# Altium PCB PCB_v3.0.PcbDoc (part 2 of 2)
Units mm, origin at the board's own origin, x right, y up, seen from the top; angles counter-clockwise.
Board outline 140 x 100 mm, 2 copper layers (Top Layer, Bottom Layer); 283 components, 163 nets, 757 pads, 121 vias.
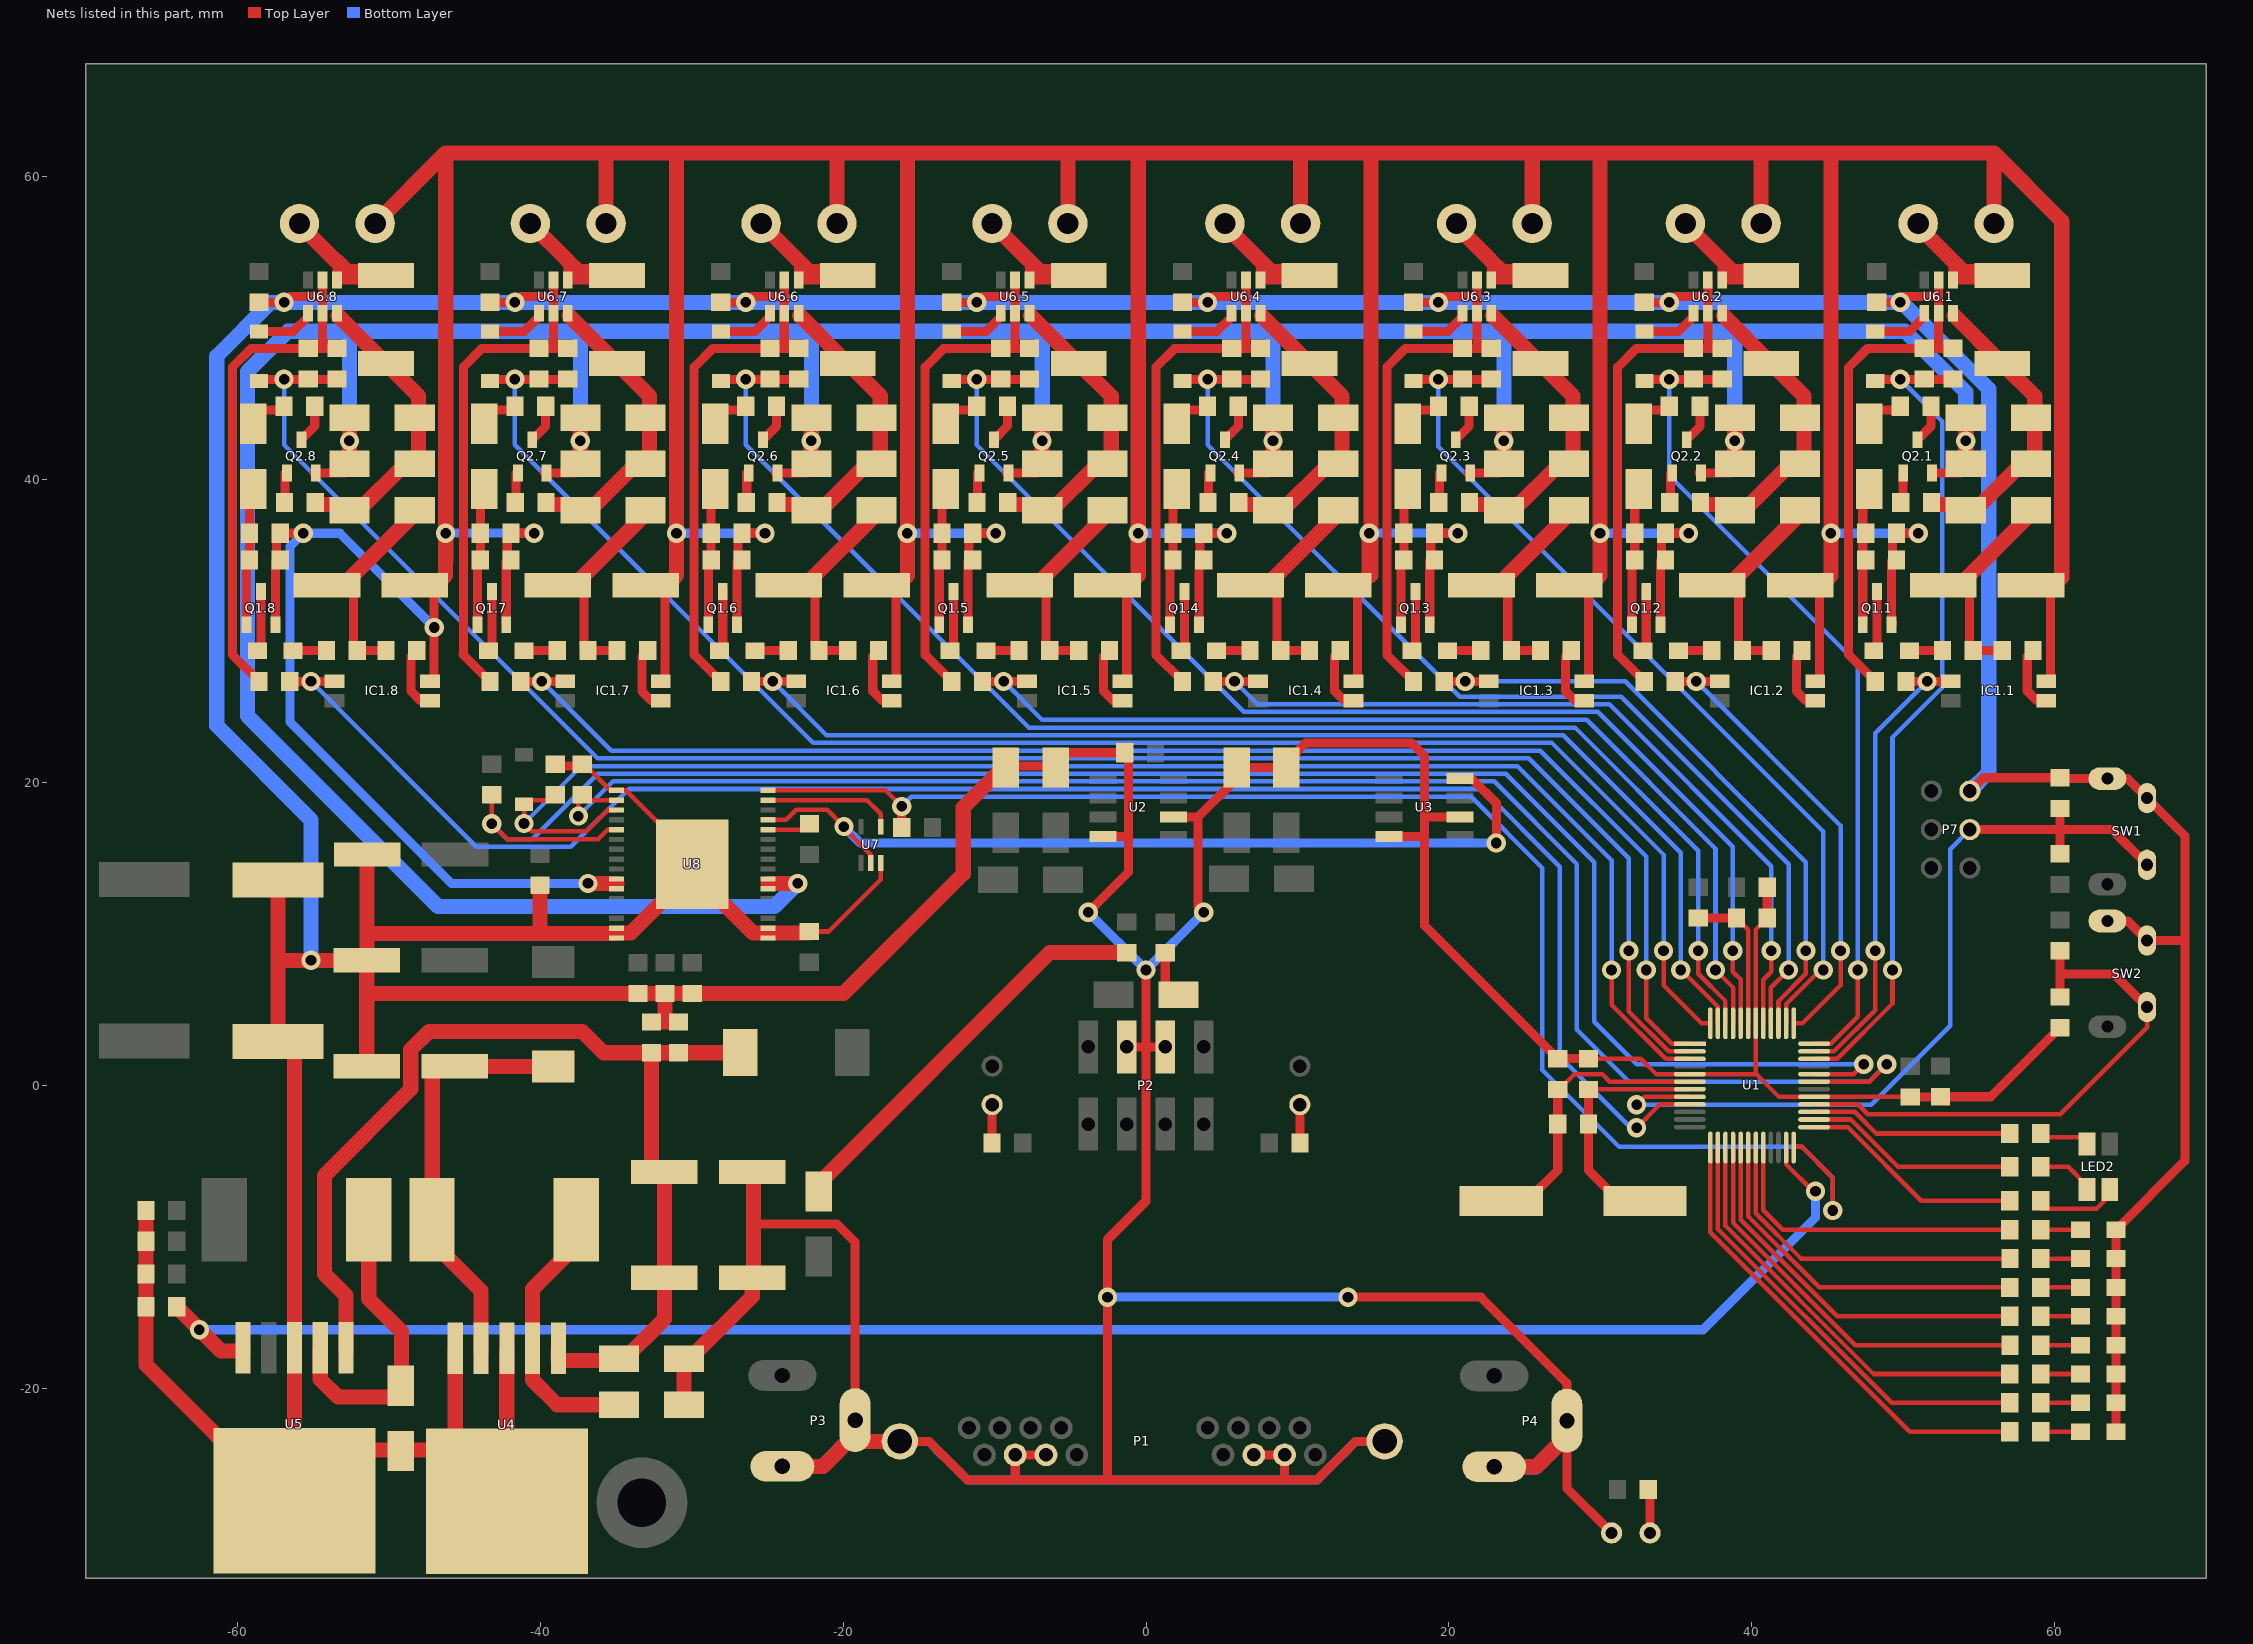
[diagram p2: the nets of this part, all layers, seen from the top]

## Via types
v1: diameter 1.27, hole 0.7, Top Layer to Bottom Layer, tented both sides, 115 vias
v2: diameter 6, hole 3.2, Top Layer to Bottom Layer, 4 vias
v3: diameter 4.05, hole 3.25, Top Layer to Bottom Layer, 2 vias

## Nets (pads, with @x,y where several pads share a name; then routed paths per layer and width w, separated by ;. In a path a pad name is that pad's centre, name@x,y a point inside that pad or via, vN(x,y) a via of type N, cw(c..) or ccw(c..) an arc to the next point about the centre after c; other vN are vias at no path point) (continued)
GND: C1.2 C2.1 C3.1 C4.2 C5.2 C6.2 C7.2 C8.2 C9.1 C10.1 C11.2 C12.2 C13.2 C14.1 C15.1 C16.1 C17.1 C18.2 C19.2 C20.2 C21.1 C22.1 C23.1 C26.1.1 C26.2.1 C26.3.1 C26.4.1 C26.5.1 C26.6.1 C26.7.1 C26.8.1 C27.1.1 C27.2.1 C27.3.1 C27.4.1 C27.5.1 C27.6.1 C27.7.1 C27.8.1 C28.1 C30.2 C31.1 D3.2 D5.1 D6.1 D7.2 D9.1 D10.1 D11.1 LED1.2 LED3.2 LED4.2 LED5.2 LED6.2 LED7.2 LED8.2 LED9.2 LED10.2 P1.0 P1.4 P1.6 P1.12 P1.14 P2.4 P2.6 P3.2 P3.3 P4.2 P4.3 P7.5 R22.1 R23.1 R29.1.1 R29.2.1 R29.3.1 R29.4.1 R29.5.1 R29.6.1 R29.7.1 R29.8.1 R32.1.1 R32.2.1 R32.3.1 R32.4.1 R32.5.1 R32.6.1 R32.7.1 R32.8.1 R33.1 SW1.1 SW1.3 SW2.1 SW2.3 U1.5 U1.29 U1.42 U2.2 U2.8 U3.2 U3.8 U4.3 U4.5 U5.3 U6.1.2 U6.1.5 U6.2.2 U6.2.5 U6.3.2 U6.3.5 U6.4.2 U6.4.5 U6.5.2 U6.5.5 U6.6.2 U6.6.5 U6.7.2 U6.7.5 U6.8.2 U6.8.5 U7.3 U8.1 U8.15 U8.16 U8.17 U8.18 U8.33 | length 1152.2
  Top Layer w0.3: R22.1@-36.956,21.081 -35.355,19.48 U8.1@-34.951,19.48 -34.335,19.48 -29.951,15.096 U8.33@-29.951,14.605 -29.951,14.118 U8.33@-29.951,14.076 ; -34.951,10.033 U8.15@-34.951,10.38 -34.626,10.055 ; -25.276,10.055 U8.18@-24.951,10.38 -24.951,10.055 ; C28.1@-22.225,10.159 -20.941,10.159 -17.511,13.589 U7.3@-17.511,14.675 U7.3@-17.511,15.056 ; C3.1@29.21,1.765 32.652,1.765 33.667,0.75 U1.5@35.9,0.75 40.271,0.75 ; C9.1@41.011,11.05 40.25,10.289 U1.42@40.25,4.1 40.25,0.771 40.271,0.75 ; C6.2@50.448,-0.765 50.433,-0.75 U1.29@44.1,-0.75 42.981,-0.75 42.981,-0.762 41.783,-0.762 40.271,0.75
  Top Layer w0.6: -60.306,28.43 -60.303,28.427 ; C26.8.1@-58.547,51.69 C26.8.1@-58.547,51.69 v1(-56.896,51.689) -56.515,52.07 -54.356,52.07 ; R29.8.1@-58.546,26.67 -60.303,28.427 ; U6.8.5@-54.356,53.17 -54.356,52.07 ; C27.8.1@-53.406,48.682 -53.447,48.641 -54.356,48.641 ; -45.067,28.43 -45.064,28.427 ; R29.7.1@-43.307,26.67 -45.064,28.427 ; C26.7.1@-43.307,51.69 C26.7.1@-43.307,51.69 v1(-41.656,51.689) -41.275,52.07 -39.116,52.07 ; U6.7.5@-39.116,53.17 -39.116,52.07 ; R33.1@-38.989,21.081 R22.1@-36.956,21.081 ; C27.7.1@-38.166,48.682 -38.207,48.641 -39.116,48.641 ; -29.827,28.43 -29.824,28.427 ; R29.6.1@-28.067,26.67 -29.824,28.427 ; C26.6.1@-28.067,51.69 C26.6.1@-28.067,51.69 v1(-26.416,51.689) -26.035,52.07 -23.876,52.07 ; -25.908,-9.144 -20.4,-9.144 -19.203,-10.341 P3.2@-19.203,-22.096 ; U6.6.5@-23.876,53.17 -23.876,52.07 ; C27.6.1@-22.926,48.682 -22.967,48.641 -23.876,48.641 ; P1.0@-16.247,-23.494 -14.331,-23.494 -11.79,-26.035 -8.632,-26.035 ; -14.586,28.43 -14.583,28.427 ; C26.5.1@-12.827,51.69 C26.5.1@-12.827,51.69 v1(-11.176,51.689) -10.795,52.07 -8.636,52.07 ; R29.5.1@-12.826,26.67 -14.583,28.427 ; D3.2@-9.327,21.082 -5.969,21.082 -5.969,21.96 -1.661,21.96 -1.396,22.225 -1.142,21.971 -1.142,16.441 ; U6.5.5@-8.636,53.17 -8.636,52.07 ; C27.5.1@-7.686,48.682 -7.727,48.641 -8.636,48.641 ; P1.6@-6.602,-24.384 P1.4@-8.632,-24.384 -8.632,-26.035 ; v1(-3.81,11.43) -1.142,14.098 -1.142,16.441 ; U2.8@-2.851,16.441 -1.142,16.441 ; P2.4@-1.27,1.397 P2.4@-1.27,2.54 0,2.54 ; v1(0,7.62) 0,2.54 ; 0.655,28.43 0.657,28.428 ; P2.6@1.27,2.54 0,2.54 ; U2.2@1.829,17.711 3.429,17.711 ; C26.4.1@2.413,51.69 C26.4.1@2.413,51.69 v1(4.064,51.689) 4.445,52.07 6.604,52.07 ; R29.4.1@2.415,26.67 0.657,28.428 ; v1(3.81,11.43) 3.429,11.811 3.429,17.711 ; U6.4.5@6.604,53.17 6.604,52.07 ; P1.12@7.118,-24.384 P1.14@9.148,-24.384 9.148,-26.035 ; C27.4.1@7.554,48.682 7.513,48.641 6.604,48.641 ; v1(13.335,-13.98) 22.108,-13.98 27.787,-19.659 P4.2@27.787,-22.127 27.787,-23.14 27.787,-26.602 LED1.2@30.73,-29.545 ; P1.0@15.753,-23.494 13.844,-23.494 12.939,-24.399 12.932,-24.399 11.453,-25.878 11.453,-25.885 11.303,-26.035 9.148,-26.035 ; 15.896,28.43 15.897,28.429 ; U3.8@16.363,16.441 18.38,16.441 ; C26.3.1@17.653,51.69 C26.3.1@17.653,51.69 v1(19.304,51.689) 19.685,52.07 21.844,52.07 ; R29.3.1@17.656,26.67 15.897,28.429 ; U3.2@20.373,17.711 18.38,17.711 ; U6.3.5@21.844,53.17 21.844,52.07 ; C27.3.1@22.794,48.682 22.753,48.641 21.844,48.641 ; C3.1@29.21,1.765 C2.1@27.178,1.765 18.38,10.563 18.38,16.441 ; C26.2.1@32.893,51.69 C26.2.1@32.893,51.69 v1(34.544,51.689) 34.925,52.07 37.084,52.07 ; R29.2.1@32.897,26.67 31.137,28.43 31.137,47.414 32.364,48.641 36.027,48.641 36.068,48.682 36.109,48.641 37.084,48.641 ; U6.2.5@37.084,53.17 37.084,52.07 ; C27.2.1@38.034,48.682 37.993,48.641 37.084,48.641 ; C9.1@41.011,11.05 C8.2@41.011,13.08 ; R29.1.1@48.138,26.67 46.377,28.431 46.377,47.393 47.625,48.641 51.267,48.641 51.308,48.682 51.349,48.641 52.324,48.641 ; C26.1.1@48.244,51.688 48.246,51.69 v1(49.784,51.69) 49.784,51.815 50.039,52.07 52.324,52.07 ; C6.2@50.448,-0.765 52.436,-0.765 C7.2@52.451,-0.75 55.764,-0.75 C5.2@60.325,3.811 ; U6.1.5@52.324,53.17 52.324,52.07 ; C27.1.1@53.274,48.682 53.233,48.641 52.324,48.641 ; P7.5@54.385,19.431 55.262,20.308 C4.2@60.325,20.308 60.383,20.25 SW1.3@63.457,20.25 64.796,20.25 SW1.1@66.083,18.964 68.58,16.467 68.58,9.566 ; SW2.3@63.457,10.852 64.796,10.852 SW2.1@66.083,9.566 68.58,9.566 ; LED10.2@64.04,-22.86 LED9.2@64.04,-20.955 LED8.2@64.04,-19.05 LED7.2@64.04,-17.145 LED6.2@64.04,-15.24 LED5.2@64.04,-13.335 LED4.2@64.04,-11.43 LED3.2@64.04,-9.525 68.58,-4.985 68.58,9.566 ; -60.303,28.427 -60.303,47.414 -59.076,48.641 -55.413,48.641 -55.372,48.682 -55.331,48.641 -54.356,48.641 ; -54.356,48.641 U6.8.2@-54.356,50.97 -54.356,52.07 ; -45.064,28.427 -45.064,46.122 -45.063,46.123 -45.063,47.414 -43.836,48.641 -40.173,48.641 -40.132,48.682 -40.091,48.641 -39.116,48.641 ; -39.116,48.641 U6.7.2@-39.116,50.97 -39.116,52.07 ; -29.824,28.427 -29.824,46.122 -29.823,46.123 -29.823,47.414 -28.596,48.641 -24.933,48.641 -24.892,48.682 -24.851,48.641 -23.876,48.641 ; -23.876,48.641 U6.6.2@-23.876,50.97 -23.876,52.07 ; -14.583,28.427 -14.583,47.414 -13.356,48.641 -9.693,48.641 -9.652,48.682 -9.611,48.641 -8.636,48.641 ; -8.636,48.641 U6.5.2@-8.636,50.97 -8.636,52.07 ; -8.632,-26.035 -2.54,-26.035 ; -2.54,-26.035 9.148,-26.035 ; -2.54,-26.035 v1(-2.54,-13.98) -2.54,-10.17 0,-7.63 0,2.54 ; 0.657,28.428 0.657,47.414 1.884,48.641 5.547,48.641 5.588,48.682 5.629,48.641 6.604,48.641 ; 3.429,17.711 5.978,20.26 D9.1@5.978,20.98 D7.2@9.271,20.98 9.77,20.98 9.77,21.837 10.539,22.606 17.526,22.606 18.38,21.752 18.38,17.711 ; 6.604,48.641 U6.4.2@6.604,50.97 6.604,52.07 ; 15.897,28.429 15.897,47.414 17.124,48.641 20.787,48.641 20.828,48.682 20.869,48.641 21.844,48.641 ; 18.38,16.441 18.38,17.711 ; 21.844,48.641 U6.3.2@21.844,50.97 21.844,52.07 ; 37.084,48.641 U6.2.2@37.084,50.97 37.084,52.07 ; 52.324,48.641 U6.1.2@52.324,50.97 52.324,52.07
  Top Layer w1: C23.1@-66.015,-12.573 R23.1@-66.015,-14.605 -66.015,-18.44 -56.829,-27.626 -56.818,-27.543 U5.3@-56.819,-27.614 ; C23.1@-66.015,-12.446 C22.1@-66.015,-10.287 C21.1@-66.015,-8.255 ; C19.2@-57.297,2.393 C19.2@-57.297,2.896 -57.297,8.255 ; C20.2@-57.297,13.564 -57.297,8.255 ; C19.2@-56.794,2.896 -56.358,2.896 -56.212,2.75 -56.212,-17.526 U5.3@-56.212,-24.061 ; U5.3@-56.339,-24.061 U5.3@-56.212,-24.061 ; U5.3@-56.212,-27.626 U5.3@-56.212,-24.061 ; C12.2@-51.435,1.27 -51.435,6.072 ; C30.2@-51.414,15.24 -51.414,10.033 ; U4.3@-45.698,-24.121 U4.3@-45.593,-24.226 ; U4.5@-45.593,-17.526 U4.3@-45.593,-24.061 ; U4.3@-42.32,-24.061 U4.3@-45.593,-24.061 ; U4.3@-42.193,-17.526 -42.193,-24.064 -42.373,-24.064 U4.3@-45.593,-24.226 ; C31.1@-40.005,13.209 -40.005,10.033 ; -34.951,10.033 -40.005,10.033 ; -34.626,10.055 -34.014,10.055 U8.33@-29.951,14.118 ; C17.1@-32.766,4.19 C17.1@-32.639,4.19 -31.75,4.19 ; C10.1@-30.734,4.19 C10.1@-30.861,4.19 -31.75,4.19 ; D10.1@-30.499,-21.209 -30.491,-21.201 -30.491,-18.161 -30.226,-18.161 -25.991,-13.926 C18.2@-25.991,-12.7 -25.991,-12.402 -25.908,-12.319 -25.908,-9.144 -25.908,-5.798 C11.2@-25.991,-5.715 ; U8.33@-29.951,14.076 -25.93,10.055 -25.276,10.055 ; -24.951,10.055 C28.1@-22.248,10.055 ; P3.3@-24.003,-25.146 -21.332,-25.146 P3.2@-19.203,-23.017 ; P3.2@-19.203,-22.096 P3.2@-19.203,-23.017 ; P1.0@-16.247,-23.494 -19.077,-23.494 -19.203,-23.368 P3.2@-19.203,-23.017 ; D3.2@-9.327,21.082 -12.063,18.346 -12.063,13.972 -19.963,6.072 C16.1@-29.951,6.072 C15.1@-31.75,6.072 ; P4.3@22.987,-25.177 25.75,-25.177 P4.2@27.787,-23.14 ; -57.297,8.255 v1(-55.118,8.255) C13.2@-51.435,8.255 ; U5.3@-56.212,-24.061 U4.3@-45.593,-24.061 ; -51.435,6.072 C14.1@-33.528,6.072 C15.1@-31.75,6.072 ; -51.435,6.072 C13.2@-51.435,8.255 ; C13.2@-51.435,8.255 -51.414,8.276 -51.414,10.033 ; -51.414,10.033 -40.005,10.033 ; U4.3@-45.593,-24.226 U4.3@-45.593,-24.061 ; -31.75,4.19 C15.1@-31.75,6.072
  Bottom Layer w0.6: P1.0@-16.247,-23.494 -14.352,-23.494 -13.447,-24.399 -13.426,-24.399 -11.79,-26.035 11.295,-26.035 12.931,-24.399 12.938,-24.399 13.843,-23.494 P1.0@15.753,-23.494 ; v1(-3.81,11.43) v1(0,7.62) v1(3.81,11.43) ; v1(-2.54,-13.98) v1(13.335,-13.98)
  Bottom Layer w1: -57.783,51.688 -57.781,51.69 ; v1(-56.896,51.689) -57.78,51.689 -57.781,51.69 ; v1(-55.118,8.255) -55.118,17.525 -61.341,23.748 -61.341,48.134 -57.785,51.69 -57.781,51.69 ; -42.543,51.688 -42.541,51.69 ; v1(-41.656,51.689) -42.54,51.689 -42.541,51.69 ; -27.303,51.688 -27.301,51.69 ; v1(-26.416,51.689) -27.3,51.689 -27.301,51.69 ; P3.3@-24.003,-25.146 -21.336,-25.146 P3.2@-19.203,-23.013 ; P3.2@-19.203,-22.096 P3.2@-19.203,-23.013 ; P1.0@-16.247,-23.494 -19.077,-23.494 -19.203,-23.368 P3.2@-19.203,-23.013 ; -12.063,51.688 -12.061,51.69 ; v1(-11.176,51.689) -12.06,51.689 -12.061,51.69 ; 3.177,51.688 3.179,51.69 ; v1(4.064,51.689) 3.18,51.689 3.179,51.69 ; 18.415,51.69 3.179,51.69 ; v1(19.304,51.689) 18.42,51.689 18.419,51.69 18.417,51.688 33.657,51.688 33.659,51.69 ; P4.3@22.987,-25.177 25.75,-25.177 27.787,-23.14 P4.2@27.787,-22.127 ; v1(34.544,51.689) 33.66,51.689 33.659,51.69 ; P7.5@54.385,19.431 55.626,20.672 55.626,45.964 49.9,51.69 49.898,51.688 49.896,51.69 v1(49.784,51.69) 33.659,51.69 ; -57.781,51.69 -42.541,51.69 ; -42.541,51.69 -27.301,51.69 ; -27.301,51.69 -12.061,51.69 ; -12.061,51.69 3.179,51.69
LED1: R10.1 U1.20 | length 20.9
  Top Layer w0.3: U1.20@40.75,-4.1 40.75,-8.238 42.037,-9.525 R10.1@57.024,-9.525
LED2: R11.1 U1.19 | length 22.4
  Top Layer w0.3: U1.19@40.25,-4.1 40.25,-8.445 43.235,-11.43 R11.1@57.029,-11.43
LED3: R12.1 U1.18 | length 23.8
  Top Layer w0.3: U1.18@39.75,-4.1 39.75,-8.652 44.433,-13.335 R12.1@57.024,-13.335
LED4: R13.1 U1.17 | length 25.2
  Top Layer w0.3: U1.17@39.25,-4.1 39.25,-8.859 45.631,-15.24 R13.1@57.024,-15.24
LED5: R14.1 U1.16 | length 26.6
  Top Layer w0.3: U1.16@38.75,-4.1 38.75,-9.066 46.829,-17.145 R14.1@57.029,-17.145
LED6: R15.1 U1.15 | length 28
  Top Layer w0.3: U1.15@38.25,-4.1 38.25,-9.274 48.026,-19.05 R15.1@57.024,-19.05
LED7: R16.1 U1.14 | length 29.4
  Top Layer w0.3: U1.14@37.75,-4.1 37.75,-9.481 49.224,-20.955 R16.1@57.024,-20.955
LED8: R17.1 U1.13 | length 30.8
  Top Layer w0.3: U1.13@37.25,-4.1 37.25,-9.688 50.422,-22.86 R17.1@57.024,-22.86
LED_B: R9.2 U1.25 | length 14.9
  Top Layer w0.3: U1.25@44.1,-2.75 46.311,-2.75 51.181,-7.62 R9.2@57.024,-7.62
LED_G: R8.2 U1.26 | length 14.2
  Top Layer w0.3: U1.26@44.1,-2.25 46.518,-2.25 49.638,-5.37 R8.2@57.024,-5.37
LED_R: R7.2 U1.27 | length 13.5
  Top Layer w0.3: U1.27@44.1,-1.75 46.775,-1.75 48.2,-3.175 R7.2@57.024,-3.175
MODE: C5.1 R20.1 SW2.2 U1.28 | length 35.7
  Top Layer w0.3: U1.28@44.1,-1.25 46.982,-1.25 47.631,-1.899 60.352,-1.899 66.083,3.832 SW2.2@66.083,5.166
  Top Layer w0.6: C5.1@60.325,5.841 60.325,7.366 ; R20.1@60.325,8.891 60.325,7.366 ; SW2.2@66.083,5.166 63.882,7.366 60.325,7.366
NetC2_2: C2.2 R21.2 U1.6 Y1.2 | length 19.4
  Top Layer w0.3: C2.2@27.178,-0.265 27.559,-0.265 27.559,0 28.309,0.75 30.111,0.75 30.611,0.25 U1.6@35.9,0.25
  Top Layer w0.6: Y1.2@23.444,-7.63 25.136,-7.63 27.179,-5.587 R21.2@27.179,-2.54 R21.2@27.179,-2.54 C2.2@27.178,-0.265
NetC3_2: C3.2 R21.1 U1.7 Y1.1 | length 16.6
  Top Layer w0.3: C3.2@29.21,-0.265 29.21,-0.25 U1.7@35.9,-0.25
  Top Layer w0.6: C3.2@29.21,-0.265 29.21,-2.539 R21.1@29.209,-2.54 29.209,-5.587 31.252,-7.63 Y1.1@32.944,-7.63
NetC9_2: C9.2 L1.2 U1.43 | length 9.8
  Top Layer w0.3: C9.2@38.981,11.05 39.75,10.281 U1.43@39.75,4.1
  Top Layer w0.6: L1.2@36.449,11.05 C9.2@38.981,11.05
NetC12_1: C12.1 L2.2 L3.1 U4.4 | length 27.9
  Top Layer w1: L2.2@-47.117,-9.144 -47.117,1.27 C12.1@-45.635,1.27 -45.614,1.249 L3.1@-39.116,1.249 ; L2.2@-46.418,-9.144 -46.418,-11.028 -43.893,-13.553 U4.4@-43.893,-17.526
NetC24.1_1: C24.1.1 D13.1.2 R25.1.2 R26.1.1 | length 15.1
  Top Layer w0.6: C24.1.1@53.715,33.02 54.36,33.02 54.36,28.955 R25.1.2@54.613,28.702 R26.1.1@56.52,28.702
  Top Layer w1: C24.1.1@52.623,33.02 53.715,33.02 D13.1.2@58.668,37.973
NetC24.1_2: C24.1.2 C24.2.2 C24.3.2 C24.4.2 C24.5.2 C24.6.2 C24.7.2 C24.8.2 C25.1.1 C25.2.1 C25.3.1 C25.4.1 C25.5.1 C25.6.1 C25.7.1 C25.8.1 IC1.1.2 IC1.2.2 IC1.3.2 IC1.4.2 IC1.5.2 IC1.6.2 IC1.7.2 IC1.8.2 P8.2 P9.2 P10.2 P11.2 P12.2 P13.2 P14.2 P15.2 Q1.1.2 Q1.2.2 Q1.3.2 Q1.4.2 Q1.5.2 Q1.6.2 Q1.7.2 Q1.8.2 R30.1.1 R30.2.1 R30.3.1 R30.4.1 R30.5.1 R30.6.1 R30.7.1 R30.8.1 U8.10 U8.11 | length 601.3
  Top Layer w0.6: Q1.8.2@-57.47,30.523 -57.47,34.615 -57.405,34.68 R30.8.1@-57.405,36.449 ; R30.8.1@-57.151,36.449 v1(-55.629,36.449) ; C24.8.2@-48.261,33.02 -46.99,33.02 v1(-46.99,30.226) -46.99,26.67 IC1.8.2@-47.269,26.67 ; Q1.7.2@-42.231,30.523 -42.231,34.615 C25.7.1@-42.166,34.68 ; C25.7.1@-42.166,34.68 R30.7.1@-42.166,36.449 ; R30.7.1@-41.912,36.449 v1(-40.39,36.449) ; C24.7.2@-33.022,33.02 -31.751,33.02 -31.751,26.67 IC1.7.2@-32.03,26.67 ; Q1.6.2@-26.991,30.523 -26.991,34.615 C25.6.1@-26.926,34.68 ; C25.6.1@-26.926,34.68 R30.6.1@-26.926,36.449 ; R30.6.1@-26.672,36.449 v1(-25.15,36.449) ; C24.6.2@-17.782,33.02 -16.511,33.02 -16.511,26.67 IC1.6.2@-16.79,26.67 ; Q1.5.2@-11.75,30.523 -11.75,34.615 -11.685,34.68 R30.5.1@-11.685,36.449 ; R30.5.1@-11.431,36.449 v1(-9.909,36.449) ; C24.5.2@-2.541,33.02 -1.27,33.02 -1.27,26.67 IC1.5.2@-1.549,26.67 ; Q1.4.2@3.491,30.523 3.491,34.615 3.556,34.68 R30.4.1@3.556,36.449 ; R30.4.1@3.81,36.449 v1(5.332,36.449) ; C24.4.2@12.7,33.02 13.971,33.02 13.971,26.67 IC1.4.2@13.692,26.67 ; Q1.3.2@18.732,30.523 18.732,34.615 18.797,34.68 R30.3.1@18.797,36.449 ; R30.3.1@19.051,36.449 v1(20.573,36.449) ; C24.3.2@27.941,33.02 29.212,33.02 29.212,26.67 IC1.3.2@28.933,26.67 ; Q1.2.2@33.973,30.523 33.973,34.615 34.038,34.68 R30.2.1@34.038,36.449 ; R30.2.1@34.292,36.449 v1(35.814,36.449) ; C24.2.2@43.182,33.02 44.453,33.02 44.453,26.67 IC1.2.2@44.174,26.67 ; Q1.1.2@49.257,30.48 49.214,30.523 49.214,34.615 49.279,34.68 R30.1.1@49.279,36.449 ; R30.1.1@49.533,36.449 49.66,36.322 49.787,36.449 v1(50.974,36.449) ; C24.1.2@58.423,33.02 59.694,33.02 59.694,26.67 IC1.1.2@59.415,26.67
  Top Layer w1: P15.2@-50.88,56.896 -46.228,61.548 ; C24.8.2@-46.99,33.02 C24.8.2@-46.866,33.02 ; C24.8.2@-46.863,33.02 C24.8.2@-46.866,33.02 ; v1(-46.231,36.449) -46.231,33.655 C24.8.2@-46.866,33.02 ; -46.228,34.671 -46.228,61.548 ; v1(-36.83,13.335) -34.925,13.335 ; P14.2@-35.64,56.896 -35.64,61.548 ; C24.7.2@-31.751,33.02 C24.7.2@-31.627,33.02 ; C24.7.2@-31.624,33.02 C24.7.2@-31.627,33.02 ; v1(-30.992,36.449) -30.992,33.655 C24.7.2@-31.627,33.02 ; C24.7.2@-30.989,33.655 -30.989,61.548 ; P13.2@-20.4,56.896 -20.4,61.548 ; C24.6.2@-16.511,33.02 C24.6.2@-16.387,33.02 ; C24.6.2@-16.384,33.02 C24.6.2@-16.387,33.02 ; v1(-15.752,36.449) -15.752,33.655 C24.6.2@-16.387,33.02 ; -15.748,34.671 -15.748,61.548 ; P12.2@-5.16,56.896 -5.16,61.548 ; C24.5.2@-1.27,33.02 C24.5.2@-1.146,33.02 ; C24.5.2@-1.143,33.02 C24.5.2@-1.146,33.02 ; v1(-0.511,36.449) -0.511,33.655 C24.5.2@-1.146,33.02 ; -0.508,34.671 -0.508,61.548 ; P11.2@10.207,56.896 10.207,61.548 ; C24.4.2@13.971,33.02 C24.4.2@14.095,33.02 ; C24.4.2@14.098,33.02 C24.4.2@14.095,33.02 ; v1(14.73,36.449) 14.73,33.655 C24.4.2@14.095,33.02 ; C24.4.2@14.859,33.655 14.859,61.548 ; P10.2@25.494,56.896 25.494,61.548 ; C24.3.2@29.212,33.02 C24.3.2@29.336,33.02 ; C24.3.2@29.339,33.02 C24.3.2@29.336,33.02 ; v1(29.971,36.449) 29.971,33.655 C24.3.2@29.336,33.02 ; 29.972,34.671 29.972,61.548 ; P9.2@40.607,56.896 40.607,61.548 ; C24.2.2@44.453,33.02 C24.2.2@44.577,33.02 ; C24.2.2@44.58,33.02 C24.2.2@44.577,33.02 ; P8.2@55.974,56.896 55.974,61.548 ; C24.1.2@59.694,33.02 59.944,33.02 60.452,33.528 60.452,57.07 55.974,61.548 ; -46.228,61.548 -35.64,61.548 ; -35.64,61.548 -30.989,61.548 ; -30.989,61.548 -20.4,61.548 ; -20.4,61.548 -15.748,61.548 ; -15.748,61.548 -5.16,61.548 ; -5.16,61.548 -0.508,61.548 ; -0.508,61.548 10.207,61.548 ; 10.207,61.548 14.859,61.548 ; 14.859,61.548 25.494,61.548 ; 25.494,61.548 29.972,61.548 ; 29.972,61.548 40.607,61.548 ; 40.607,61.548 45.212,61.548 ; C24.2.2@44.577,33.02 45.212,33.655 v1(45.212,36.449) 45.212,61.294 45.339,61.421 45.212,61.548 ; 45.212,61.548 55.974,61.548
  Bottom Layer w0.6: v1(-46.99,30.226) -53.213,36.449 v1(-55.629,36.449) -56.515,35.563 -56.515,24.003 -45.847,13.335 v1(-36.83,13.335) ; v1@-46.219,36.458 v1@-40.39,36.458 ; v1@-30.988,36.449 v1(-25.15,36.449) ; v1@-15.748,36.449 v1(-9.909,36.449) ; v1@-0.508,36.449 v1(5.332,36.449) ; v1@14.741,36.458 v1@20.573,36.458 ; v1@29.98,36.449 v1(35.814,36.449) ; v1(45.212,36.449) v1(50.974,36.449)
NetC24.2_1: C24.2.1 D13.2.2 R25.2.2 R26.2.1 | length 15.1
  Top Layer w0.6: C24.2.1@38.474,33.02 39.119,33.02 39.119,28.955 R25.2.2@39.372,28.702 R26.2.1@41.279,28.702
  Top Layer w1: C24.2.1@37.382,33.02 38.474,33.02 D13.2.2@43.427,37.973
NetC24.3_1: C24.3.1 D13.3.2 R25.3.2 R26.3.1 | length 15.1
  Top Layer w0.6: C24.3.1@23.233,33.02 23.878,33.02 23.878,28.955 R25.3.2@24.131,28.702 R26.3.1@26.038,28.702
  Top Layer w1: C24.3.1@22.141,33.02 23.233,33.02 D13.3.2@28.186,37.973
NetC24.4_1: C24.4.1 D13.4.2 R25.4.2 R26.4.1 | length 15.1
  Top Layer w0.6: C24.4.1@7.992,33.02 8.637,33.02 8.637,28.955 R25.4.2@8.89,28.702 R26.4.1@10.797,28.702
  Top Layer w1: C24.4.1@6.9,33.02 7.992,33.02 D13.4.2@12.945,37.973
NetC24.5_1: C24.5.1 D13.5.2 R25.5.2 R26.5.1 | length 15.1
  Top Layer w0.6: C24.5.1@-7.249,33.02 -6.604,33.02 -6.604,28.955 R25.5.2@-6.351,28.702 R26.5.1@-4.444,28.702
  Top Layer w1: C24.5.1@-8.341,33.02 -7.249,33.02 D13.5.2@-2.296,37.973
NetC24.6_1: C24.6.1 D13.6.2 R25.6.2 R26.6.1 | length 15.1
  Top Layer w0.6: C24.6.1@-22.49,33.02 -21.845,33.02 -21.845,28.955 R25.6.2@-21.592,28.702 R26.6.1@-19.685,28.702
  Top Layer w1: C24.6.1@-23.582,33.02 -22.49,33.02 D13.6.2@-17.537,37.973
NetC24.7_1: C24.7.1 D13.7.2 R25.7.2 R26.7.1 | length 15.1
  Top Layer w0.6: C24.7.1@-37.73,33.02 -37.085,33.02 -37.085,28.955 R25.7.2@-36.832,28.702 R26.7.1@-34.925,28.702
  Top Layer w1: C24.7.1@-38.822,33.02 -37.73,33.02 D13.7.2@-32.777,37.973
NetC24.8_1: C24.8.1 D13.8.2 R25.8.2 R26.8.1 | length 15.1
  Top Layer w0.6: C24.8.1@-52.969,33.02 -52.324,33.02 -52.324,28.955 R25.8.2@-52.071,28.702 R26.8.1@-50.164,28.702
  Top Layer w1: C24.8.1@-54.061,33.02 -52.969,33.02 D13.8.2@-48.016,37.973
NetC25.1_2: C25.1.2 D15.1.2 Q1.1.1 R30.1.2 | length 9
  Top Layer w0.6: Q1.1.1@47.314,30.523 47.314,36.449 47.314,39.064 D15.1.2@47.629,39.379
NetC25.2_2: C25.2.2 D15.2.2 Q1.2.1 R30.2.2 | length 9.1
  Top Layer w0.6: Q1.2.1@32.073,30.4 32.073,34.491 C25.2.2@32.262,34.68 32.262,36.449 32.262,39.253 D15.2.2@32.388,39.379
NetC25.3_2: C25.3.2 D15.3.2 Q1.3.1 R30.3.2 | length 9.1
  Top Layer w0.6: Q1.3.1@16.832,30.4 16.832,34.491 C25.3.2@17.021,34.68 17.021,36.449 17.021,39.253 D15.3.2@17.147,39.379
NetC25.4_2: C25.4.2 D15.4.2 Q1.4.1 R30.4.2 | length 9.1
  Top Layer w0.6: Q1.4.1@1.591,30.4 1.591,34.491 C25.4.2@1.78,34.68 1.78,36.449 1.78,39.253 D15.4.2@1.906,39.379
NetC25.5_2: C25.5.2 D15.5.2 Q1.5.1 R30.5.2 | length 9.1
  Top Layer w0.6: Q1.5.1@-13.65,30.4 -13.65,34.491 C25.5.2@-13.461,34.68 -13.461,36.449 -13.461,39.253 D15.5.2@-13.335,39.379
NetC25.6_2: C25.6.2 D15.6.2 Q1.6.1 R30.6.2 | length 9.1
  Top Layer w0.6: Q1.6.1@-28.891,30.4 -28.891,34.491 C25.6.2@-28.702,34.68 -28.702,36.449 -28.702,39.253 D15.6.2@-28.576,39.379
NetC25.7_2: C25.7.2 D15.7.2 Q1.7.1 R30.7.2 | length 9.1
  Top Layer w0.6: Q1.7.1@-44.131,30.4 -44.131,34.491 C25.7.2@-43.942,34.68 -43.942,36.449 -43.942,39.253 D15.7.2@-43.816,39.379
NetC25.8_2: C25.8.2 D15.8.2 Q1.8.1 R30.8.2 | length 9.1
  Top Layer w0.6: Q1.8.1@-59.37,30.4 -59.37,34.491 C25.8.2@-59.181,34.68 -59.181,36.449 -59.181,39.253 D15.8.2@-59.055,39.379
NetC27.1_2: C27.1.2 D16.1.2 R32.1.2 U1.34 | length 55.7
  Top Layer w0.3: U1.34@44.1,1.75 45.62,1.75 49.276,5.406 v1(49.276,7.62)
  Top Layer w0.6: D16.1.2@48.133,46.498 48.244,46.609 v1(49.784,46.609) R32.1.2@51.13,46.609 ; R32.1.2@51.241,46.498 R32.1.2@51.13,46.609 ; C27.1.2@53.274,46.631 53.252,46.609 R32.1.2@51.13,46.609
  Bottom Layer w0.3: v1(49.276,7.62) 49.276,22.987 52.547,26.258 52.547,43.846 v1(49.784,46.609)
NetC27.2_2: C27.2.2 D16.2.2 R32.2.2 U1.36 | length 56.2
  Top Layer w0.3: U1.36@44.1,2.75 45.206,2.75 46.99,4.534 v1(46.99,7.619)
  Top Layer w0.6: D16.2.2@32.897,46.498 33.008,46.609 v1(34.544,46.609) R32.2.2@35.89,46.609 ; R32.2.2@35.779,46.498 R32.2.2@35.89,46.609 ; C27.2.2@38.034,46.631 38.012,46.609 R32.2.2@35.89,46.609
  Bottom Layer w0.3: v1(34.544,46.609) 34.544,40.259 46.99,27.813 v1(46.99,7.619)
NetC27.3_2: C27.3.2 D16.3.2 R32.3.2 U1.38 | length 59.5
  Top Layer w0.3: U1.38@42.25,4.1 42.25,5.352 44.517,7.619 v1(44.704,7.619)
  Top Layer w0.6: D16.3.2@17.657,46.498 17.768,46.609 v1(19.304,46.609) R32.3.2@20.65,46.609 ; R32.3.2@20.539,46.498 R32.3.2@20.65,46.609 ; C27.3.2@22.794,46.631 22.772,46.609 R32.3.2@20.65,46.609
  Bottom Layer w0.3: v1(19.304,46.609) 19.304,42.164 44.704,16.764 v1(44.704,7.619)
NetC27.4_2: C27.4.2 D16.4.2 R32.4.2 U1.40 | length 70.5
  Top Layer w0.3: U1.40@41.25,4.1 41.25,6.452 v1(42.418,7.62)
  Top Layer w0.6: D16.4.2@2.417,46.498 2.528,46.609 v1(4.064,46.609) R32.4.2@5.41,46.609 ; R32.4.2@5.299,46.498 R32.4.2@5.41,46.609 ; C27.4.2@7.554,46.631 7.532,46.609 R32.4.2@5.41,46.609
  Bottom Layer w0.3: v1(4.064,46.609) 4.064,42.291 20.701,25.654 31.369,25.654 42.418,14.605 v1(42.418,7.62)
NetC27.5_2: C27.5.2 D16.5.2 R32.5.2 U1.44 | length 82.4
  Top Layer w0.3: v1(38.735,8.891) 38.735,7.508 39.25,6.993 U1.44@39.25,4.1
  Top Layer w0.6: D16.5.2@-12.823,46.498 -12.712,46.609 v1(-11.176,46.609) R32.5.2@-9.83,46.609 ; R32.5.2@-9.941,46.498 R32.5.2@-9.83,46.609 ; C27.5.2@-7.686,46.631 -7.708,46.609 R32.5.2@-9.83,46.609
  Bottom Layer w0.3: v1(-11.176,46.609) -11.176,42.273 6.443,24.654 29.829,24.654 38.735,15.748 v1(38.735,8.891)
NetC27.6_2: C27.6.2 D16.6.2 R32.6.2 U1.46 | length 95.8
  Top Layer w0.3: v1(36.449,8.889) 36.449,7.369 38.25,5.568 U1.46@38.25,4.1
  Top Layer w0.6: D16.6.2@-28.063,46.498 -27.952,46.609 v1(-26.416,46.609) R32.6.2@-25.07,46.609 ; R32.6.2@-25.181,46.498 R32.6.2@-25.07,46.609 ; C27.6.2@-22.926,46.631 -22.948,46.609 R32.6.2@-25.07,46.609
  Bottom Layer w0.3: v1(-26.416,46.609) -26.416,42.291 -7.747,23.622 28.321,23.622 36.449,15.494 v1(36.449,8.889)
NetC27.7_2: C27.7.2 D16.7.2 R32.7.2 U1.48 | length 109.5
  Top Layer w0.3: v1(34.163,8.891) 34.163,6.604 36.667,4.1 U1.48@37.25,4.1
  Top Layer w0.6: D16.7.2@-43.303,46.498 -43.192,46.609 v1(-41.656,46.609) R32.7.2@-40.31,46.609 ; R32.7.2@-40.421,46.498 R32.7.2@-40.31,46.609 ; C27.7.2@-38.166,46.631 -38.188,46.609 R32.7.2@-40.31,46.609
  Bottom Layer w0.3: v1@-41.657,46.609 -41.657,42.292 -21.971,22.606 26.797,22.606 34.163,15.24 v1(34.163,8.891)
NetC27.8_2: C27.8.2 D16.8.2 R32.8.2 U1.2 | length 124.9
  Top Layer w0.3: v1(31.877,8.891) 31.877,4.881 34.508,2.25 U1.2@35.9,2.25
  Top Layer w0.6: D16.8.2@-58.543,46.498 -58.432,46.609 v1(-56.896,46.609) R32.8.2@-55.55,46.609 ; R32.8.2@-55.661,46.498 R32.8.2@-55.55,46.609 ; C27.8.2@-53.406,46.631 -53.428,46.609 R32.8.2@-55.55,46.609
  Bottom Layer w0.3: v1@-56.896,46.565 -56.896,42.291 -36.203,21.598 25.265,21.598 31.877,14.986 v1(31.877,8.891)
NetC29_2: C29.2 U8.28 | length 2.9
  Top Layer w0.3: U8.28@-24.951,16.88 -22.609,16.88 C29.2@-22.218,17.271
NetD1_2: D1.2 R1.2 | length 27.1
  Top Layer w1: D1.2@-21.59,-6.994 -21.59,-6.477 -6.349,8.764 R1.2@-1.27,8.764
NetD2_2: D2.2 R2.2 | length 3.6
  Top Layer w0.6: R2.2@1.27,8.764 1.27,6.072 1.373,5.969 D2.2@2.148,5.969
NetD10_2: D10.2 L2.1 U4.2 | length 18.2
  Top Layer w1: L2.1@-36.893,-9.144 -36.893,-9.842 -40.493,-13.442 -40.493,-17.526 -40.493,-19.451 -38.862,-21.082 D10.2@-34.789,-21.082
NetD11_2: D11.2 L4.1 U5.2 | length 20
  Top Layer w1: U5.2@-54.512,-17.526 -54.512,-19.402 -53.34,-20.574 -49.149,-20.574 -49.149,-19.821 -49.149,-16.256 -51.308,-14.097 L4.1@-51.308,-9.144
NetD12.1_1: D12.1.1 D13.1.1 D14.1.2 R27.1.2 R31.1.1 U6.1.3 | length 20.4
  Top Layer w1: R27.1.2@51.827,38.608 52.081,38.354 53.987,38.354 54.368,37.973 54.741,37.973 57.789,41.021 D12.1.1@58.415,41.021 58.668,41.021 58.668,45.497 58.664,45.497 R31.1.1@56.515,47.646 U6.1.3@53.349,50.812
NetD12.1_2: D12.1.2 D12.2.2 D12.3.2 D12.4.2 D12.5.2 D12.6.2 D12.7.2 D12.8.2 D14.1.1 D14.2.1 D14.3.1 D14.4.1 D14.5.1 D14.6.1 D14.7.1 D14.8.1 Q2.1.2 Q2.2.2 Q2.3.2 Q2.4.2 Q2.5.2 Q2.6.2 Q2.7.2 Q2.8.2 U8.22 U8.23 | length 286.9
  Top Layer w0.6: Q2.8.2@-54.931,40.429 Q2.8.2@-54.803,40.429 -52.908,40.429 D12.8.2@-52.316,41.021 ; Q2.7.2@-39.692,40.429 Q2.7.2@-39.564,40.429 -37.669,40.429 D12.7.2@-37.077,41.021 ; Q2.6.2@-24.452,40.429 Q2.6.2@-24.324,40.429 -22.429,40.429 D12.6.2@-21.837,41.021 ; Q2.5.2@-9.211,40.429 Q2.5.2@-9.083,40.429 -7.188,40.429 D12.5.2@-6.596,41.021 ; Q2.4.2@6.03,40.429 Q2.4.2@6.158,40.429 8.053,40.429 D12.4.2@8.645,41.021 ; Q2.3.2@21.271,40.429 Q2.3.2@21.399,40.429 23.294,40.429 D12.3.2@23.886,41.021 ; Q2.2.2@36.512,40.429 Q2.2.2@36.64,40.429 38.535,40.429 D12.2.2@39.127,41.021 ; Q2.1.2@51.881,40.429 53.776,40.429 D12.1.2@54.368,41.021
  Top Layer w1: D12.8.2@-52.569,41.021 -52.581,41.033 D12.8.2@-52.581,41.286 ; D14.8.1@-52.569,44.069 -52.581,44.057 v1(-52.581,42.545) D12.8.2@-52.581,41.286 ; D12.8.2@-52.316,41.021 D12.8.2@-52.581,41.286 ; D12.7.2@-37.33,41.021 -37.342,41.033 D12.7.2@-37.342,41.286 ; D14.7.1@-37.33,44.069 -37.342,44.057 v1(-37.342,42.545) D12.7.2@-37.342,41.286 ; D12.7.2@-37.077,41.021 D12.7.2@-37.342,41.286 ; -24.951,13.335 v1(-22.987,13.335) ; D12.6.2@-22.09,41.021 -22.102,41.033 D12.6.2@-22.102,41.286 ; D14.6.1@-22.09,44.069 -22.102,44.057 v1(-22.102,42.545) D12.6.2@-22.102,41.286 ; D12.6.2@-21.837,41.021 D12.6.2@-22.102,41.286 ; D12.5.2@-6.849,41.021 -6.861,41.033 D12.5.2@-6.861,41.286 ; D14.5.1@-6.849,44.069 -6.861,44.057 v1(-6.861,42.545) D12.5.2@-6.861,41.286 ; D12.5.2@-6.596,41.021 D12.5.2@-6.861,41.286 ; D12.4.2@8.392,41.021 8.38,41.033 D12.4.2@8.38,41.286 ; D14.4.1@8.392,44.069 8.38,44.057 v1(8.38,42.545) D12.4.2@8.38,41.286 ; D12.4.2@8.645,41.021 D12.4.2@8.38,41.286 ; D12.3.2@23.633,41.021 23.621,41.033 D12.3.2@23.621,41.286 ; D14.3.1@23.633,44.069 23.621,44.057 v1(23.621,42.545) D12.3.2@23.621,41.286 ; D12.3.2@23.886,41.021 D12.3.2@23.621,41.286 ; D12.2.2@38.874,41.021 38.862,41.033 D12.2.2@38.862,41.286 ; D14.2.1@38.874,44.069 38.862,44.057 v1(38.862,42.545) D12.2.2@38.862,41.286 ; D12.2.2@39.127,41.021 D12.2.2@38.862,41.286 ; D14.1.1@54.115,44.069 v1(54.115,42.545) 54.115,41.274 D12.1.2@54.368,41.021
  Bottom Layer w1: v1@-52.569,42.545 -52.569,49.784 ; v1@-37.33,42.545 -37.33,49.784 ; v1(-22.987,13.335) -24.511,11.811 -46.736,11.811 -59.309,24.384 -59.309,47.117 -56.642,49.784 -52.569,49.784 ; v1@-22.09,42.545 -22.09,49.784 ; v1@-6.849,42.545 -6.849,49.784 ; v1@8.392,42.545 8.392,49.784 ; v1@23.633,42.545 23.633,49.784 ; v1(38.862,42.545) 38.862,49.772 38.874,49.784 ; v1(54.115,42.545) 54.115,45.778 50.109,49.784 38.874,49.784 ; -52.569,49.784 -37.33,49.784 ; -37.33,49.784 -22.09,49.784 ; -22.09,49.784 -6.849,49.784 ; -6.849,49.784 8.392,49.784 ; 8.392,49.784 23.633,49.784 ; 23.633,49.784 38.874,49.784
NetD12.2_1: D12.2.1 D13.2.1 D14.2.2 R27.2.2 R31.2.1 U6.2.3 | length 20.4
  Top Layer w1: R27.2.2@36.586,38.608 36.84,38.354 38.746,38.354 39.127,37.973 39.5,37.973 42.548,41.021 D12.2.1@43.174,41.021 43.427,41.021 43.427,45.497 43.424,45.497 R31.2.1@41.275,47.646 U6.2.3@38.109,50.812
NetD12.3_1: D12.3.1 D13.3.1 D14.3.2 R27.3.2 R31.3.1 U6.3.3 | length 20.4
  Top Layer w1: R27.3.2@21.345,38.608 21.599,38.354 23.505,38.354 23.886,37.973 24.259,37.973 27.307,41.021 D12.3.1@27.933,41.021 28.186,41.021 28.186,45.497 28.183,45.497 ; U6.3.3@22.869,50.812 R31.3.1@26.035,47.646 28.184,45.497
NetD12.4_1: D12.4.1 D13.4.1 D14.4.2 R27.4.2 R31.4.1 U6.4.3 | length 20.4
  Top Layer w1: R27.4.2@6.104,38.608 6.358,38.354 8.264,38.354 8.645,37.973 9.018,37.973 12.066,41.021 D12.4.1@12.692,41.021 12.945,41.021 12.945,45.497 12.942,45.497 ; U6.4.3@7.629,50.812 R31.4.1@10.795,47.646 12.944,45.497
NetD12.5_1: D12.5.1 D13.5.1 D14.5.2 R27.5.2 R31.5.1 U6.5.3 | length 20.4
  Top Layer w1: R27.5.2@-9.137,38.608 -8.883,38.354 -6.977,38.354 -6.596,37.973 -6.223,37.973 -3.175,41.021 D12.5.1@-2.549,41.021 -2.296,41.021 -2.296,45.497 ; U6.5.3@-7.611,50.812 R31.5.1@-4.445,47.646 -2.296,45.497 ; -2.299,45.497 -2.296,45.497
NetD12.6_1: D12.6.1 D13.6.1 D14.6.2 R27.6.2 R31.6.1 U6.6.3 | length 20.4
  Top Layer w1: R27.6.2@-24.378,38.608 -24.124,38.354 -22.218,38.354 -21.837,37.973 -21.464,37.973 -18.416,41.021 D12.6.1@-17.79,41.021 -17.537,41.021 -17.537,45.497 -17.54,45.497 ; U6.6.3@-22.851,50.812 R31.6.1@-19.685,47.646 -17.537,45.498
NetD12.7_1: D12.7.1 D13.7.1 D14.7.2 R27.7.2 R31.7.1 U6.7.3 | length 20.4
  Top Layer w1: R27.7.2@-39.618,38.608 -39.364,38.354 -37.458,38.354 -37.077,37.973 -36.704,37.973 -33.656,41.021 D12.7.1@-33.03,41.021 -32.777,41.021 -32.777,45.497 -32.78,45.497 ; U6.7.3@-38.091,50.812 R31.7.1@-34.925,47.646 -32.777,45.498
NetD12.8_1: D12.8.1 D13.8.1 D14.8.2 R27.8.2 R31.8.1 U6.8.3 | length 20.4
  Top Layer w1: R27.8.2@-54.857,38.608 -54.603,38.354 -52.697,38.354 -52.316,37.973 -51.943,37.973 -48.895,41.021 D12.8.1@-48.269,41.021 -48.016,41.021 -48.016,45.497 ; U6.8.3@-53.331,50.812 R31.8.1@-50.165,47.646 -48.016,45.497 ; -48.019,45.497 -48.016,45.497
NetD15.1_1: D15.1.1 R28.1.1 | length 3
  Top Layer w0.6: D15.1.1@47.756,43.679 47.756,44.577 49.531,44.577 R28.1.1@49.785,44.831
NetD15.2_1: D15.2.1 R28.2.1 | length 3
  Top Layer w0.6: D15.2.1@32.515,43.679 32.515,44.577 34.291,44.577 R28.2.1@34.545,44.831
NetD15.3_1: D15.3.1 R28.3.1 | length 3
  Top Layer w0.6: D15.3.1@17.274,43.679 17.274,44.577 19.05,44.577 R28.3.1@19.304,44.831
NetD15.4_1: D15.4.1 R28.4.1 | length 3
  Top Layer w0.6: D15.4.1@2.033,43.679 2.033,44.577 3.809,44.577 R28.4.1@4.063,44.831
NetD15.5_1: D15.5.1 R28.5.1 | length 3
  Top Layer w0.6: D15.5.1@-13.208,43.679 -13.208,44.577 -11.432,44.577 R28.5.1@-11.178,44.831
NetD15.6_1: D15.6.1 R28.6.1 | length 3
  Top Layer w0.6: D15.6.1@-28.449,43.679 -28.449,44.577 -26.673,44.577 R28.6.1@-26.419,44.831
NetD15.7_1: D15.7.1 R28.7.1 | length 3
  Top Layer w0.6: D15.7.1@-43.689,43.679 -43.689,44.577 -41.913,44.577 R28.7.1@-41.659,44.831
NetD15.8_1: D15.8.1 R28.8.1 | length 3
  Top Layer w0.6: D15.8.1@-58.928,43.679 -58.928,44.577 -57.152,44.577 R28.8.1@-56.898,44.831
NetD16.1_1: D16.1.1 U6.1.1 | length 3.9
  Top Layer w0.6: D16.1.1@48.133,49.768 50.403,49.768 51.374,50.739 U6.1.1@51.374,50.97
NetD16.2_1: D16.2.1 U6.2.1 | length 3.9
  Top Layer w0.6: D16.2.1@32.897,49.768 35.163,49.768 36.134,50.739 U6.2.1@36.134,50.97
NetD16.3_1: D16.3.1 U6.3.1 | length 3.9
  Top Layer w0.6: D16.3.1@17.657,49.768 19.923,49.768 20.894,50.739 U6.3.1@20.894,50.97
NetD16.4_1: D16.4.1 U6.4.1 | length 3.9
  Top Layer w0.6: D16.4.1@2.417,49.768 4.683,49.768 5.654,50.739 U6.4.1@5.654,50.97
NetD16.5_1: D16.5.1 U6.5.1 | length 3.9
  Top Layer w0.6: D16.5.1@-12.823,49.768 -10.557,49.768 -9.586,50.739 U6.5.1@-9.586,50.97
NetD16.6_1: D16.6.1 U6.6.1 | length 3.9
  Top Layer w0.6: D16.6.1@-28.063,49.768 -25.797,49.768 -24.826,50.739 U6.6.1@-24.826,50.97
NetD16.7_1: D16.7.1 U6.7.1 | length 3.9
  Top Layer w0.6: D16.7.1@-43.303,49.768 -41.037,49.768 -40.066,50.739 U6.7.1@-40.066,50.97
NetD16.8_1: D16.8.1 U6.8.1 | length 3.9
  Top Layer w0.6: D16.8.1@-58.543,49.768 -56.277,49.768 -55.306,50.739 U6.8.1@-55.306,50.97
NetD17_1: D17.1 R33.2 U1.3 U8.3 | length 102.6
  Top Layer w0.3: R33.2@-38.989,19.051 -39.21,18.83 -40.784,18.83 D17.1@-41.056,18.558 v1(-41.056,17.288) -40.532,16.764 -36.957,16.764 -35.541,18.18 U8.3@-34.951,18.18 ; v1(30.73,7.62) 30.73,5.321 34.301,1.75 U1.3@35.9,1.75
  Bottom Layer w0.3: v1(-41.056,17.288) -37.262,21.082 24.511,21.082 30.73,14.863 v1(30.73,7.62)
NetIC1.1_1: IC1.1.1 R26.1.2 | length 4.3
  Top Layer w0.6: R26.1.2@58.55,28.702 58.17,28.322 58.17,26.034 58.804,25.4 IC1.1.1@59.415,25.4
NetIC1.1_3: IC1.1.3 R29.1.2 U1.35 | length 31.2
  Top Layer w0.3: U1.35@44.1,2.25 45.413,2.25 48.133,4.97 v1(48.133,8.89)
  Top Layer w0.6: R29.1.2@50.168,26.67 v1(51.562,26.67) IC1.1.3@53.115,26.67
  Bottom Layer w0.3: v1(48.133,8.89) 48.133,23.241 v1(51.562,26.67)
NetIC1.2_1: IC1.2.1 R26.2.2 | length 4.3
  Top Layer w0.6: R26.2.2@43.309,28.702 42.929,28.322 42.929,26.034 43.563,25.4 IC1.2.1@44.174,25.4
NetIC1.2_3: IC1.2.3 R29.2.2 U1.37 | length 31.1
  Top Layer w0.3: U1.37@42.75,4.1 43.333,4.1 45.847,6.614 v1(45.847,8.89)
  Top Layer w0.6: R29.2.2@34.927,26.67 v1(36.322,26.67) IC1.2.3@37.874,26.67
  Bottom Layer w0.3: v1(36.322,26.67) 45.847,17.145 v1(45.847,8.89)
NetIC1.3_1: IC1.3.1 R26.3.2 | length 4.3
  Top Layer w0.6: R26.3.2@28.068,28.702 27.688,28.322 27.688,26.033 28.321,25.4 IC1.3.1@28.933,25.4
NetIC1.3_3: IC1.3.3 R29.3.2 U1.39 | length 41.8
  Top Layer w0.3: U1.39@41.75,4.1 41.75,5.559 43.561,7.37 v1(43.561,8.89)
  Top Layer w0.6: R29.3.2@19.686,26.67 v1(21.081,26.67) IC1.3.3@22.633,26.67
  Bottom Layer w0.3: v1(21.081,26.67) 31.625,26.67 43.561,14.734 v1(43.561,8.89)
NetIC1.4_1: IC1.4.1 R26.4.2 | length 4.3
  Top Layer w0.6: R26.4.2@12.827,28.702 12.447,28.322 12.447,26.034 13.081,25.4 IC1.4.1@13.692,25.4
NetIC1.4_3: IC1.4.3 R29.4.2 U1.41 | length 54
  Top Layer w0.3: U1.41@40.75,4.1 40.75,6.978 41.268,7.496 v1(41.268,8.889)
  Top Layer w0.6: R29.4.2@4.445,26.67 v1(5.84,26.67) IC1.4.3@7.392,26.67
  Bottom Layer w0.3: v1(5.84,26.67) 7.356,25.154 30.592,25.154 41.268,14.478 v1(41.268,8.889)
NetIC1.5_1: IC1.5.1 R26.5.2 | length 4.3
  Top Layer w0.6: R26.5.2@-2.414,28.702 -2.794,28.322 -2.794,26.026 -2.168,25.4 IC1.5.1@-1.549,25.4
NetIC1.5_3: IC1.5.3 R29.5.2 U1.45 | length 66.7
  Top Layer w0.3: v1(37.592,7.619) 38.75,6.461 U1.45@38.75,4.1
  Top Layer w0.6: R29.5.2@-10.796,26.67 v1(-9.401,26.67) IC1.5.3@-7.849,26.67
  Bottom Layer w0.3: v1(-9.401,26.67) -6.861,24.13 29.083,24.13 37.592,15.621 v1(37.592,7.619) v1@37.434,7.777
NetIC1.6_1: IC1.6.1 R26.6.2 | length 4.3
  Top Layer w0.6: R26.6.2@-17.655,28.702 -18.035,28.322 -18.035,26.036 -17.399,25.4 IC1.6.1@-16.79,25.4
NetIC1.6_3: IC1.6.3 R29.6.2 U1.47 | length 79.9
  Top Layer w0.3: v1(35.306,7.619) 35.338,7.619 37.75,5.207 U1.47@37.75,4.1
  Top Layer w0.6: R29.6.2@-26.037,26.67 v1(-24.642,26.67) IC1.6.3@-23.09,26.67
  Bottom Layer w0.3: v1(-24.642,26.67) -21.094,23.122 27.551,23.122 35.306,15.367 v1(35.306,7.619)
NetIC1.7_1: IC1.7.1 R26.7.2 | length 4.3
  Top Layer w0.6: R26.7.2@-32.895,28.702 -33.275,28.322 -33.275,26.026 -32.649,25.4 IC1.7.1@-32.03,25.4
NetIC1.7_3: IC1.7.3 R29.7.2 U1.1 | length 94.9
  Top Layer w0.3: v1(33.023,7.619) 33.023,4.442 34.715,2.75 U1.1@35.9,2.75
  Top Layer w0.6: R29.7.2@-41.277,26.67 v1(-39.882,26.67) IC1.7.3@-38.33,26.67
  Bottom Layer w0.3: v1@-39.88,26.672 -35.306,22.098 26.035,22.098 33.023,15.11 v1(33.023,7.619)
NetIC1.8_1: IC1.8.1 R26.8.2 | length 4.3
  Top Layer w0.6: R26.8.2@-48.134,28.702 -48.514,28.322 -48.514,26.026 -47.888,25.4 IC1.8.1@-47.269,25.4
NetIC1.8_3: IC1.8.3 R29.8.2 U1.9 | length 117.3
  Top Layer w0.3: v1(32.385,-2.794) 33.929,-1.25 U1.9@35.9,-1.25
  Top Layer w0.6: R29.8.2@-56.516,26.67 v1(-55.121,26.67) IC1.8.3@-53.569,26.67
  Bottom Layer w0.3: v1(-55.121,26.67) -44.207,15.756 -37.965,15.756 -34.155,19.566 22.184,19.566 27.305,14.445 27.305,1.905 32.004,-2.794 v1(32.385,-2.794)
NetLED1_1: LED1.1 R3.1 | length 3
  Top Layer w0.6: R3.1@33.088,-26.67 33.27,-26.852 LED1.1@33.27,-29.545
NetLED2_2: LED2.2 R9.1 | length 6
  Top Layer w0.3: R9.1@59.054,-7.62 59.054,-8.128 62.754,-8.128 63.813,-7.068 LED2.2@63.615,-6.87
NetLED2_3: LED2.3 R8.1 | length 3.8
  Top Layer w0.3: R8.1@59.054,-5.37 60.869,-5.37 62.115,-6.616 LED2.3@62.115,-6.87
NetLED2_4: LED2.4 R7.1 | length 3.3
  Top Layer w0.3: R7.1@59.054,-3.175 59.308,-3.429 61.674,-3.429 LED2.4@62.115,-3.87
NetLED3_1: LED3.1 R10.2 | length 2.6
  Top Layer w0.3: R10.2@59.054,-9.525 LED3.1@61.69,-9.525
NetLED4_1: LED4.1 R11.2 | length 2.6
  Top Layer w0.3: R11.2@59.059,-11.43 LED4.1@61.69,-11.43
NetLED5_1: LED5.1 R12.2 | length 2.6
  Top Layer w0.3: R12.2@59.054,-13.335 LED5.1@61.69,-13.335
NetLED6_1: LED6.1 R13.2 | length 2.6
  Top Layer w0.3: R13.2@59.054,-15.24 LED6.1@61.69,-15.24
NetLED7_1: LED7.1 R14.2 | length 2.6
  Top Layer w0.3: R14.2@59.059,-17.145 LED7.1@61.69,-17.145
NetLED8_1: LED8.1 R15.2 | length 2.6
  Top Layer w0.3: R15.2@59.054,-19.05 LED8.1@61.69,-19.05
NetLED9_1: LED9.1 R16.2 | length 2.6
  Top Layer w0.3: R16.2@59.054,-20.955 LED9.1@61.69,-20.955
NetLED10_1: LED10.1 R17.2 | length 2.6
  Top Layer w0.3: R17.2@59.054,-22.86 LED10.1@61.69,-22.86
NetLED11.1_1: LED11.1.1 R25.1.1 | length 2.2
  Top Layer w0.6: LED11.1.1@50.389,28.702 R25.1.1@52.583,28.702
NetLED11.1_2: LED11.1.2 Q1.1.3 | length 4.1
  Top Layer w0.6: LED11.1.2@48.039,28.702 48.264,28.927 Q1.1.3@48.264,32.723
NetLED11.2_1: LED11.2.1 R25.2.1 | length 2.2
  Top Layer w0.6: LED11.2.1@35.148,28.702 R25.2.1@37.342,28.702
NetLED11.2_2: LED11.2.2 Q1.2.3 | length 4.1
  Top Layer w0.6: LED11.2.2@32.798,28.702 33.023,28.927 Q1.2.3@33.023,32.723
NetLED11.3_1: LED11.3.1 R25.3.1 | length 2.2
  Top Layer w0.6: LED11.3.1@19.907,28.702 R25.3.1@22.101,28.702
NetLED11.3_2: LED11.3.2 Q1.3.3 | length 4.1
  Top Layer w0.6: LED11.3.2@17.557,28.702 17.782,28.927 Q1.3.3@17.782,32.723
NetLED11.4_1: LED11.4.1 R25.4.1 | length 2.2
  Top Layer w0.6: LED11.4.1@4.666,28.702 R25.4.1@6.86,28.702
NetLED11.4_2: LED11.4.2 Q1.4.3 | length 4.1
  Top Layer w0.6: LED11.4.2@2.316,28.702 2.541,28.927 Q1.4.3@2.541,32.723
NetLED11.5_1: LED11.5.1 R25.5.1 | length 2.2
  Top Layer w0.6: LED11.5.1@-10.575,28.702 R25.5.1@-8.381,28.702
NetLED11.5_2: LED11.5.2 Q1.5.3 | length 4.1
  Top Layer w0.6: LED11.5.2@-12.925,28.702 -12.7,28.927 Q1.5.3@-12.7,32.723
NetLED11.6_1: LED11.6.1 R25.6.1 | length 2.2
  Top Layer w0.6: LED11.6.1@-25.816,28.702 R25.6.1@-23.622,28.702
NetLED11.6_2: LED11.6.2 Q1.6.3 | length 4.1
  Top Layer w0.6: LED11.6.2@-28.166,28.702 -27.941,28.927 Q1.6.3@-27.941,32.723
NetLED11.7_1: LED11.7.1 R25.7.1 | length 2.2
  Top Layer w0.6: LED11.7.1@-41.056,28.702 R25.7.1@-38.862,28.702
NetLED11.7_2: LED11.7.2 Q1.7.3 | length 4.1
  Top Layer w0.6: LED11.7.2@-43.406,28.702 -43.181,28.927 Q1.7.3@-43.181,32.723
NetLED11.8_1: LED11.8.1 R25.8.1 | length 2.2
  Top Layer w0.6: LED11.8.1@-56.295,28.702 R25.8.1@-54.101,28.702
NetLED11.8_2: LED11.8.2 Q1.8.3 | length 4.1
  Top Layer w0.6: LED11.8.2@-58.645,28.702 -58.42,28.927 Q1.8.3@-58.42,32.723
NetP5_1: P5.1 R4.1 | length 2.5
  Top Layer w0.6: P5.1@-10.16,-1.27 -10.159,-1.271 R4.1@-10.159,-3.81
NetP6_1: P6.1 R5.1 | length 2.5
  Top Layer w0.6: P6.1@10.16,-1.27 10.16,-3.807 R5.1@10.163,-3.81
NetP8_1: P8.1 R31.1.2 U6.1.4 | length 11.8
  Top Layer w0.6: 53.213,54.483 53.274,54.422 U6.1.4@53.274,53.17 56.239,53.17 R31.1.2@56.515,53.446
  Top Layer w1: P8.1@50.8,56.896 53.213,54.483 ; 53.274,54.422 53.975,53.721 56.24,53.721 R31.1.2@56.515,53.446
NetP9_1: P9.1 R31.2.2 U6.2.4 | length 11.8
  Top Layer w0.6: 37.973,54.483 38.034,54.422 U6.2.4@38.034,53.17 40.999,53.17 R31.2.2@41.275,53.446
  Top Layer w1: P9.1@35.56,56.896 37.973,54.483 ; 38.034,54.422 38.735,53.721 41,53.721 R31.2.2@41.275,53.446
NetP10_1: P10.1 R31.3.2 U6.3.4 | length 11.8
  Top Layer w0.6: 22.733,54.483 22.794,54.422 U6.3.4@22.794,53.17 25.759,53.17 R31.3.2@26.035,53.446
  Top Layer w1: P10.1@20.32,56.896 22.733,54.483 ; 22.794,54.422 23.495,53.721 25.76,53.721 R31.3.2@26.035,53.446
NetP11_1: P11.1 R31.4.2 U6.4.4 | length 11.8
  Top Layer w0.6: 7.493,54.483 7.554,54.422 U6.4.4@7.554,53.17 10.519,53.17 R31.4.2@10.795,53.446
  Top Layer w1: P11.1@5.08,56.896 7.493,54.483 ; 7.554,54.422 8.255,53.721 10.52,53.721 R31.4.2@10.795,53.446
NetP12_1: P12.1 R31.5.2 U6.5.4 | length 11.8
  Top Layer w0.6: -7.747,54.483 -7.686,54.422 U6.5.4@-7.686,53.17 -4.721,53.17 R31.5.2@-4.445,53.446
  Top Layer w1: P12.1@-10.16,56.896 -7.747,54.483 ; -7.686,54.422 -6.985,53.721 -4.72,53.721 R31.5.2@-4.445,53.446
NetP13_1: P13.1 R31.6.2 U6.6.4 | length 11.8
  Top Layer w0.6: -22.987,54.483 -22.926,54.422 U6.6.4@-22.926,53.17 -19.961,53.17 R31.6.2@-19.685,53.446
  Top Layer w1: P13.1@-25.4,56.896 -22.987,54.483 ; -22.926,54.422 -22.225,53.721 -19.96,53.721 R31.6.2@-19.685,53.446
NetP14_1: P14.1 R31.7.2 U6.7.4 | length 11.8
  Top Layer w0.6: -38.227,54.483 -38.166,54.422 U6.7.4@-38.166,53.17 -35.201,53.17 R31.7.2@-34.925,53.446
  Top Layer w1: P14.1@-40.62,56.896 -38.207,54.483 ; -38.166,54.422 -37.465,53.721 -35.2,53.721 R31.7.2@-34.925,53.446
NetP15_1: P15.1 R31.8.2 U6.8.4 | length 11.8
  Top Layer w0.6: -53.467,54.483 -53.406,54.422 U6.8.4@-53.406,53.17 -50.441,53.17 R31.8.2@-50.165,53.446
  Top Layer w1: P15.1@-55.88,56.835 -53.467,54.422 ; -53.406,54.422 -52.705,53.721 -50.44,53.721 R31.8.2@-50.165,53.446
NetQ2.1_1: Q2.1.1 R27.1.1 | length 2
  Top Layer w0.6: R27.1.1@49.813,38.481 49.981,38.649 Q2.1.1@49.981,40.429
NetQ2.1_3: Q2.1.3 R28.1.2 | length 2.6
  Top Layer w0.6: Q2.1.3@50.931,42.629 51.815,43.513 R28.1.2@51.815,44.831
NetQ2.2_1: Q2.2.1 R27.2.1 | length 2
  Top Layer w0.6: R27.2.1@34.548,38.481 34.612,38.545 Q2.2.1@34.612,40.429
NetQ2.2_3: Q2.2.3 R28.2.2 | length 2.6
  Top Layer w0.6: Q2.2.3@35.69,42.629 36.575,43.514 R28.2.2@36.575,44.831
NetQ2.3_1: Q2.3.1 R27.3.1 | length 2
  Top Layer w0.6: R27.3.1@19.307,38.481 19.371,38.545 Q2.3.1@19.371,40.429
NetQ2.3_3: Q2.3.3 R28.3.2 | length 2.6
  Top Layer w0.6: Q2.3.3@20.449,42.629 21.334,43.514 R28.3.2@21.334,44.831
NetQ2.4_1: Q2.4.1 R27.4.1 | length 2
  Top Layer w0.6: R27.4.1@4.066,38.481 4.13,38.545 Q2.4.1@4.13,40.429
NetQ2.4_3: Q2.4.3 R28.4.2 | length 2.6
  Top Layer w0.6: Q2.4.3@5.208,42.629 6.093,43.514 R28.4.2@6.093,44.831
NetQ2.5_1: Q2.5.1 R27.5.1 | length 2
  Top Layer w0.6: R27.5.1@-11.175,38.481 -11.111,38.545 Q2.5.1@-11.111,40.429
NetQ2.5_3: Q2.5.3 R28.5.2 | length 2.6
  Top Layer w0.6: Q2.5.3@-10.033,42.629 -9.148,43.514 R28.5.2@-9.148,44.831
NetQ2.6_1: Q2.6.1 R27.6.1 | length 2
  Top Layer w0.6: R27.6.1@-26.416,38.481 -26.352,38.545 Q2.6.1@-26.352,40.429
NetQ2.6_3: Q2.6.3 R28.6.2 | length 2.6
  Top Layer w0.6: Q2.6.3@-25.274,42.629 -24.389,43.514 R28.6.2@-24.389,44.831
NetQ2.7_1: Q2.7.1 R27.7.1 | length 2
  Top Layer w0.6: R27.7.1@-41.656,38.481 -41.592,38.545 Q2.7.1@-41.592,40.429
NetQ2.7_3: Q2.7.3 R28.7.2 | length 2.6
  Top Layer w0.6: Q2.7.3@-40.514,42.629 -39.629,43.514 R28.7.2@-39.629,44.831
NetQ2.8_1: Q2.8.1 R27.8.1 | length 2
  Top Layer w0.6: R27.8.1@-56.895,38.481 -56.831,38.545 Q2.8.1@-56.831,40.429
NetQ2.8_3: Q2.8.3 R28.8.2 | length 2.6
  Top Layer w0.6: Q2.8.3@-55.753,42.629 -54.868,43.514 R28.8.2@-54.868,44.831
NetR18_1: R18.1 U1.32 U8.5 | length 121.3
  Top Layer w0.3: R18.1@-43.181,19.235 -43.18,19.234 v1(-43.18,17.272) -42.164,16.256 -36.171,16.256 -35.547,16.88 U8.5@-34.951,16.88 ; U1.32@44.1,0.75 46.724,0.75 v1(47.371,1.397)
  Bottom Layer w0.3: v1(-43.18,17.272) -42.164,16.256 -40.513,16.256 -36.195,20.574 23.749,20.574 29.591,14.732 29.591,4.191 32.385,1.397 v1(47.371,1.397)
NetR22_2: R22.2 U1.31 U8.2 | length 111.6
  Top Layer w0.3: v1(-37.465,17.78) -37.465,18.924 R22.2@-37.211,19.178 -36.863,18.83 U8.2@-34.951,18.83 ; U1.31@44.1,0.25 47.748,0.25 v1(48.895,1.397)
  Bottom Layer w0.3: v1(-37.465,17.78) -35.179,20.066 22.987,20.066 28.448,14.605 28.448,3.668 31.862,0.254 47.752,0.254 v1(48.895,1.397)
NetR23_2: R23.2 U1.23 U5.5 | length 120.8
  Top Layer w0.3: U1.23@42.25,-4.1 42.25,-5.207 44.037,-6.994 v1(44.196,-6.994)
  Top Layer w1: R23.2@-63.985,-14.605 -61.064,-17.526 U5.5@-59.612,-17.526
  Bottom Layer w0.6: v1(-62.484,-16.129) 36.767,-16.129 44.196,-8.7 v1(44.196,-6.994)
NetR32_1: R32.1 U1.24 U8.32 | length 98.4
  Top Layer w0.3: U8.32@-24.951,19.48 -17.194,19.48 v1(-16.129,18.415) ; U1.24@42.75,-4.1 42.786,-4.064 43.307,-4.064 45.339,-6.096 v1(45.339,-8.255)
  Top Layer w0.6: v1(-16.129,18.415) -16.128,18.414 R32.1@-16.128,17.018
  Bottom Layer w0.3: v1(-16.129,18.415) -15.494,19.05 21.463,19.05 26.162,14.351 26.162,1.016 31.242,-4.064 43.307,-4.064 45.339,-6.096 v1(45.339,-8.255)
NetU3_4: U3.4 U7.2 U8.29 | length 57.4
  Top Layer w0.3: U8.29@-24.951,17.53 -23.747,17.53 -23.086,18.191 -21.046,18.191 v1(-19.939,17.084) -19.939,16.998 -18.161,15.22 U7.2@-18.161,15.03
  Top Layer w0.6: U3.4@21.043,20.251 21.516,20.251 23.123,18.644 23.123,16.011 v1(23.114,16.002)
  Bottom Layer w0.6: v1(-19.939,17.084) -18.857,16.002 v1(23.114,16.002) v1@23.123,16.002
NetU7_4: U7.4 U8.31 | length 8.3
  Top Layer w0.3: U8.31@-24.951,18.83 -18.419,18.83 -17.511,17.922 U7.4@-17.511,17.43
POWER: C10.2 C11.1 C17.2 C18.1 D6.2 R6.2 U4.1 U5.1 | length 72.8
  Top Layer w1: U5.1@-52.812,-17.526 -52.812,-13.863 -54.229,-12.446 -54.229,-5.941 -48.535,-0.247 -48.535,2.36 -47.339,3.556 -37.211,3.556 -35.815,2.16 C17.2@-32.639,2.16 ; U4.1@-38.793,-17.526 -38.793,-18.161 -34.544,-18.161 -31.791,-15.408 C18.1@-31.791,-12.7 C11.1@-31.791,-5.715 -32.639,-5.715 C17.2@-32.639,2.16 ; R6.2@-26.786,2.16 C10.2@-30.861,2.16 C17.2@-32.639,2.16
RESET: C4.1 P7.3 R19.1 SW1.2 U1.8 | length 55.7
  Top Layer w0.3: v1(32.385,-1.27) 32.905,-0.75 U1.8@35.9,-0.75
  Top Layer w0.6: P7.3@54.385,16.891 60.325,16.891 ; R19.1@60.325,15.295 60.325,16.891 ; C4.1@60.325,18.278 60.325,16.891 ; SW1.2@66.083,14.564 63.756,16.891 60.325,16.891
  Bottom Layer w0.3: v1(32.385,-1.27) 47.879,-1.27 53.086,3.937 53.086,15.592 P7.3@54.385,16.891
pads on no net: P7.2 P7.4 SW1.4 SW2.4 U1.10 U1.11 U1.12 U2.5 U3.1 U3.5 U7.1 U8.4 U8.6 U8.9 U8.12 U8.13 U8.14 U8.19 U8.20 U8.21 U8.24 U8.27 U8.30
copper on no net:
  other v2: -65,-27.545 65,-27.545 -65,62.455 65,62.455
  other v3: -14.472,-26.924 13.978,-26.924

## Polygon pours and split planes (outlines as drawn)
GND on Bottom Layer "BottomLayer-GND" (solid, pour order 2): -70,-32.545 -69.977,-32.522 -69.977,67.455 -70,67.455 70,67.455 70,-32.545
GND on Top Layer "TopLayer-GND" (solid, pour order 0): -70,-32.545 -69.977,-32.522 -69.977,67.455 -70,67.455 70,67.455 70,-32.545

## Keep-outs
Keep-Out Layer:
  lines w0.1: -70.002,-32.537 -70.002,67.437 70.002,67.437 70.002,-32.537 -70.002,-32.537

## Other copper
Top Layer:
  text "ALBRECHT" at 39.372,-27.94 h3
  text "DCC Repeater v3.0" at 39.372,-30.48 h2.54
Bottom Layer:
  text "DCC Repeater v3.0" at 60.325,-30.48 h2.54

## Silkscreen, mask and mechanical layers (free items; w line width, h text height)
Top Overlay:
  lines w0.254: 60.96,25.259 60.96,24.13 69.85,24.13 69.85,25.259 ; 60.96,54.102 60.96,55.324 69.85,55.324 69.85,54.102
  text "CH.8" at -46.736,62.484 h1.27 r90
  text "CH.7" at -31.496,62.484 h1.27 r90
  text "CH.6" at -16.247,62.484 h1.27 r90
  text "CH.3" at 29.591,62.484 h1.27 r90
  text "CH.2" at 44.704,62.484 h1.27 r90
  text "CH.5" at -1.016,62.455 h1.27 r90
  text "CH.4" at 14.351,62.455 h1.27 r90
  text "CH.1" at 60.071,62.455 h1.27 r90
  text "<== 8x" at 61.849,55.88 h1.27
  text "RESET" at 62.23,21.59 h1.27
  text "PROG" at 50.8,11.303 h1.27
  text "CAN" at -11.811,3.048 h1.27
  text "DCC" at 8.509,3.048 h1.27
  text "MODE" at 62.992,1.27 h1.27
  text "STAT" at 69.469,-7.747 h1.27 r90
  text "CH.1" at 65.067,-10.16 h1.27
  text "CH.2" at 65.067,-12.065 h1.27
  text "CH.3" at 65.151,-13.97 h1.27
  text "CH.4" at 65.151,-15.875 h1.27
  text "CH.5" at 65.151,-17.78 h1.27
  text "24V" at -19.685,-17.907 h1.27 r90
  text "24V" at 19.939,-17.907 h1.27 r90
  text "CH.6" at 65.151,-19.685 h1.27
  text "CH.7" at 65.151,-21.59 h1.27
  text "CH.8" at 65.151,-23.494 h1.27
  text "POWER" at 29.083,-25.273 h1.27
  text "ALBRECHT" at 39.372,-27.94 h3
  text "DCC Repeater v3.0" at 39.37,-30.48 h2.54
